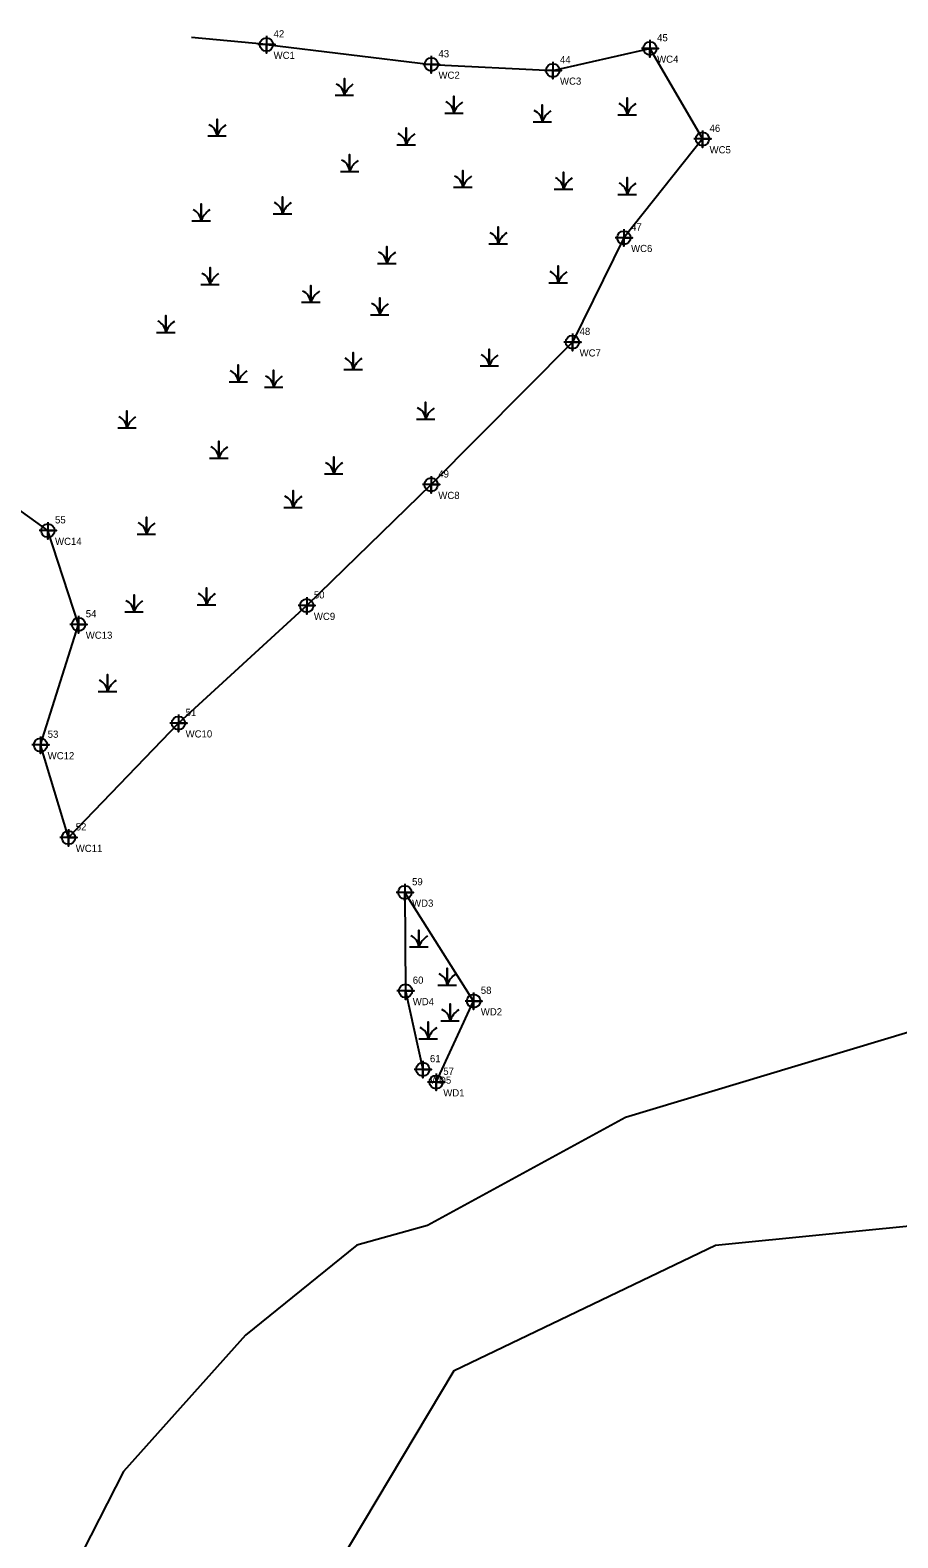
# Model space of a CAD drawing. Extents: x 2189822 to 2191198, y 387253 to 388663.
# Drawn here: x 2190593 to 2190896, y 388137 to 388663 of the extents above; entities that cross this region are included whole.
import ezdxf

# ---------------------------------------------------------------- set-up
doc = ezdxf.new("R2010")
doc.units = 0
for name, color, linetype in [('Structure020030_Alleghany', 7, 'Continuous'), ('Structure040008_Ashe', 7, 'Continuous'), ('Structure090007_Brunswick', 7, 'Continuous'), ('Structure300012_Duplin', 7, 'Continuous'), ('Structure620024_Moore', 7, 'Continuous'), ('Structure780124_Rockingham', 7, 'Continuous')]:
    doc.layers.add(name, color=color, linetype=linetype)

msp = doc.modelspace()

# ---------------------------------------------------------------- linework, layer by layer
at = {"layer": 'Structure020030_Alleghany'}
for points in [[(2190675.12, 388660.89), (2190675.12, 388654.89), (2190675.12, 388657.89), (2190678.12, 388657.89), (2190672.12, 388657.89)], [(2190808.98, 388659.55), (2190808.98, 388653.55), (2190808.98, 388656.55), (2190811.98, 388656.55), (2190805.98, 388656.55)], [(2190732.67, 388653.96), (2190732.67, 388647.96), (2190732.67, 388650.96), (2190735.67, 388650.96), (2190729.67, 388650.96)], [(2190775.08, 388651.89), (2190775.08, 388645.89), (2190775.08, 388648.89), (2190778.08, 388648.89), (2190772.08, 388648.89)], [(2190827.29, 388627.95), (2190827.29, 388621.95), (2190827.29, 388624.95), (2190830.29, 388624.95), (2190824.29, 388624.95)], [(2190799.88, 388593.51), (2190799.88, 388587.51), (2190799.88, 388590.51), (2190802.88, 388590.51), (2190796.88, 388590.51)], [(2190781.92, 388557.07), (2190781.92, 388551.07), (2190781.92, 388554.07), (2190784.92, 388554.07), (2190778.92, 388554.07)], [(2190732.61, 388507.35), (2190732.61, 388501.35), (2190732.61, 388504.35), (2190735.61, 388504.35), (2190729.61, 388504.35)], [(2190598.83, 388491.32), (2190598.83, 388485.32), (2190598.83, 388488.32), (2190601.83, 388488.32), (2190595.83, 388488.32)], [(2190689.18, 388465.15), (2190689.18, 388459.15), (2190689.18, 388462.15), (2190692.18, 388462.15), (2190686.18, 388462.15)], [(2190609.56, 388458.58), (2190609.56, 388452.58), (2190609.56, 388455.58), (2190612.56, 388455.58), (2190606.56, 388455.58)], [(2190644.41, 388424.14), (2190644.41, 388418.14), (2190644.41, 388421.14), (2190647.41, 388421.14), (2190641.41, 388421.14)], [(2190596.27, 388416.53), (2190596.27, 388410.53), (2190596.27, 388413.53), (2190599.27, 388413.53), (2190593.27, 388413.53)], [(2190606.06, 388384.2), (2190606.06, 388378.2), (2190606.06, 388381.2), (2190609.06, 388381.2), (2190603.06, 388381.2)], [(2190723.45, 388365.09), (2190723.45, 388359.09), (2190723.45, 388362.09), (2190726.45, 388362.09), (2190720.45, 388362.09)], [(2190723.69, 388330.73), (2190723.69, 388324.73), (2190723.69, 388327.73), (2190726.69, 388327.73), (2190720.69, 388327.73)], [(2190747.44, 388327.19), (2190747.44, 388321.19), (2190747.44, 388324.19), (2190750.44, 388324.19), (2190744.44, 388324.19)], [(2190729.69, 388303.35), (2190729.69, 388297.35), (2190729.69, 388300.35), (2190732.69, 388300.35), (2190726.69, 388300.35)], [(2190734.34, 388298.92), (2190734.34, 388292.92), (2190734.34, 388295.92), (2190737.34, 388295.92), (2190731.34, 388295.92)]]:
    msp.add_lwpolyline(points, dxfattribs=at)
for centre in [(2190675.12, 388657.89), (2190808.98, 388656.55), (2190732.67, 388650.96), (2190775.08, 388648.89), (2190827.29, 388624.95), (2190799.88, 388590.51), (2190781.92, 388554.07), (2190732.61, 388504.35), (2190598.83, 388488.32), (2190689.18, 388462.15), (2190609.56, 388455.58), (2190644.41, 388421.14), (2190596.27, 388413.53), (2190606.06, 388381.2), (2190723.45, 388362.09), (2190723.69, 388327.73), (2190747.44, 388324.19), (2190729.69, 388300.35), (2190734.34, 388295.92)]:
    msp.add_circle(centre, 2.34, dxfattribs=at)
at = {"layer": 'Structure300012_Duplin'}
for points in [[(2190719.63, 387525.44), (2190637.58, 387595.81), (2190615.99, 387660.63), (2190664.72, 387734.09), (2190719.01, 387832.86), (2190706.67, 387885.95), (2190672.74, 388022.38), (2190691.25, 388112.51), (2190740.6, 388195.23), (2190831.91, 388239.06), (2190949.74, 388250.79), (2191071.27, 388298.94), (2191159.49, 388358.82), (2191198.36, 388416.84)], [(2190909.02, 388316.22), (2190800.44, 388283.5), (2190731.35, 388245.85), (2190706.67, 388239.06), (2190667.81, 388207.57), (2190625.24, 388160.04), (2190596.86, 388104.48), (2190598.1, 388023), (2190601.8, 387934.1), (2190635.11, 387861.26), (2190644.98, 387808.17), (2190567.25, 387745.2), (2190533.32, 387681), (2190546.89, 387613.72), (2190580.2, 387545.81), (2190636.96, 387481.61), (2190661.02, 387459.39)]]:
    msp.add_lwpolyline(points, dxfattribs=at)
at = {"layer": 'Structure620024_Moore'}
msp.add_line((2190675.12, 388657.89), (2190648.98, 388660.35), dxfattribs=at)
for points in [[(2190675.12, 388657.89), (2190732.67, 388650.96), (2190775.08, 388648.89), (2190808.98, 388656.55), (2190827.29, 388624.95), (2190799.88, 388590.51), (2190781.92, 388554.07), (2190732.61, 388504.35), (2190689.18, 388462.15), (2190644.41, 388421.14), (2190606.06, 388381.2), (2190596.27, 388413.53), (2190609.56, 388455.58), (2190598.83, 388488.32), (2190554.41, 388520.35)], [(2190734.34, 388295.92), (2190747.44, 388324.19), (2190723.45, 388362.09), (2190723.69, 388327.73), (2190729.69, 388300.35)]]:
    msp.add_lwpolyline(points, dxfattribs=at)
at = {"layer": 'Structure780124_Rockingham'}
for p, q in [((2190702.31, 388642.87), (2190702.31, 388642.87)), ((2190740.56, 388636.7), (2190740.56, 388636.7)), ((2190771.41, 388633.61), (2190771.41, 388633.61)), ((2190801.02, 388636.08), (2190801.02, 388636.08)), ((2190657.9, 388628.67), (2190657.9, 388628.67)), ((2190723.91, 388625.58), (2190723.91, 388625.58)), ((2190704.17, 388616.32), (2190704.17, 388616.32)), ((2190743.65, 388610.77), (2190743.65, 388610.77)), ((2190778.81, 388610.15), (2190778.81, 388610.15)), ((2190801.02, 388608.3), (2190801.02, 388608.3)), ((2190680.72, 388601.51), (2190680.72, 388601.51)), ((2190652.34, 388599.04), (2190652.34, 388599.04)), ((2190755.99, 388591.01), (2190755.99, 388591.01)), ((2190717.12, 388584.22), (2190717.12, 388584.22)), ((2190655.43, 388576.82), (2190655.43, 388576.82)), ((2190776.96, 388577.43), (2190776.96, 388577.43)), ((2190690.59, 388570.64), (2190690.59, 388570.64)), ((2190714.65, 388566.32), (2190714.65, 388566.32)), ((2190640.01, 388560.15), (2190640.01, 388560.15)), ((2190705.4, 388547.18), (2190705.4, 388547.18)), ((2190752.9, 388548.42), (2190752.9, 388548.42)), ((2190665.3, 388542.86), (2190665.3, 388542.86)), ((2190677.64, 388541.01), (2190677.64, 388541.01)), ((2190730.69, 388529.9), (2190730.69, 388529.9)), ((2190626.43, 388526.81), (2190626.43, 388526.81)), ((2190658.51, 388516.32), (2190658.51, 388516.32)), ((2190698.61, 388510.76), (2190698.61, 388510.76)), ((2190684.42, 388499.03), (2190684.42, 388499.03)), ((2190633.22, 388489.77), (2190633.22, 388489.77)), ((2190654.19, 388465.08), (2190654.19, 388465.08)), ((2190628.9, 388462.61), (2190628.9, 388462.61)), ((2190619.65, 388434.83), (2190619.65, 388434.83)), ((2190728.34, 388345.73), (2190728.34, 388345.73)), ((2190738.21, 388332.42), (2190738.21, 388332.42)), ((2190739.22, 388319.92), (2190739.22, 388319.92)), ((2190731.56, 388313.68), (2190731.56, 388313.68))]:
    msp.add_line(p, q, dxfattribs=at)
for points in [[(2190699.09, 388640.19), (2190702.32, 388640.19), (2190702.32, 388646.11), (2190702.32, 388640.19), (2190705.54, 388640.19)], [(2190737.34, 388634.02), (2190740.56, 388634.02), (2190740.56, 388639.94), (2190740.56, 388634.02), (2190743.79, 388634.02)], [(2190797.8, 388633.4), (2190801.02, 388633.4), (2190801.02, 388639.32), (2190801.02, 388633.4), (2190804.25, 388633.4)], [(2190768.18, 388630.93), (2190771.41, 388630.93), (2190771.41, 388636.85), (2190771.41, 388630.93), (2190774.64, 388630.93)], [(2190654.67, 388626), (2190657.9, 388626), (2190657.9, 388631.91), (2190657.9, 388626), (2190661.12, 388626)], [(2190720.68, 388622.91), (2190723.91, 388622.91), (2190723.91, 388628.83), (2190723.91, 388622.91), (2190727.13, 388622.91)], [(2190700.94, 388613.65), (2190704.17, 388613.65), (2190704.17, 388619.57), (2190704.17, 388613.65), (2190707.39, 388613.65)], [(2190740.42, 388608.09), (2190743.65, 388608.09), (2190743.65, 388614.01), (2190743.65, 388608.09), (2190746.87, 388608.09)], [(2190775.59, 388607.48), (2190778.81, 388607.48), (2190778.81, 388613.39), (2190778.81, 388607.48), (2190782.04, 388607.48)], [(2190797.8, 388605.62), (2190801.02, 388605.62), (2190801.02, 388611.54), (2190801.02, 388605.62), (2190804.25, 388605.62)], [(2190649.12, 388596.36), (2190652.34, 388596.36), (2190652.34, 388602.28), (2190652.34, 388596.36), (2190655.57, 388596.36)], [(2190677.5, 388598.83), (2190680.72, 388598.83), (2190680.72, 388604.75), (2190680.72, 388598.83), (2190683.95, 388598.83)], [(2190752.76, 388588.34), (2190755.99, 388588.34), (2190755.99, 388594.26), (2190755.99, 388588.34), (2190759.21, 388588.34)], [(2190713.9, 388581.55), (2190717.12, 388581.55), (2190717.12, 388587.47), (2190717.12, 388581.55), (2190720.35, 388581.55)], [(2190773.74, 388574.76), (2190776.96, 388574.76), (2190776.96, 388580.68), (2190776.96, 388574.76), (2190780.19, 388574.76)], [(2190652.2, 388574.14), (2190655.43, 388574.14), (2190655.43, 388580.06), (2190655.43, 388574.14), (2190658.65, 388574.14)], [(2190687.37, 388567.97), (2190690.59, 388567.97), (2190690.59, 388573.89), (2190690.59, 388567.97), (2190693.82, 388567.97)], [(2190711.43, 388563.65), (2190714.65, 388563.65), (2190714.65, 388569.56), (2190714.65, 388563.65), (2190717.88, 388563.65)], [(2190636.78, 388557.47), (2190640.01, 388557.47), (2190640.01, 388563.39), (2190640.01, 388557.47), (2190643.23, 388557.47)], [(2190702.17, 388544.51), (2190705.4, 388544.51), (2190705.4, 388550.43), (2190705.4, 388544.51), (2190708.63, 388544.51)], [(2190749.68, 388545.75), (2190752.9, 388545.75), (2190752.9, 388551.66), (2190752.9, 388545.75), (2190756.13, 388545.75)], [(2190662.07, 388540.19), (2190665.3, 388540.19), (2190665.3, 388546.11), (2190665.3, 388540.19), (2190668.53, 388540.19)], [(2190674.41, 388538.34), (2190677.64, 388538.34), (2190677.64, 388544.25), (2190677.64, 388538.34), (2190680.86, 388538.34)], [(2190727.47, 388527.23), (2190730.69, 388527.23), (2190730.69, 388533.14), (2190730.69, 388527.23), (2190733.92, 388527.23)], [(2190623.21, 388524.14), (2190626.43, 388524.14), (2190626.43, 388530.06), (2190626.43, 388524.14), (2190629.66, 388524.14)], [(2190655.29, 388513.64), (2190658.51, 388513.64), (2190658.51, 388519.56), (2190658.51, 388513.64), (2190661.74, 388513.64)], [(2190695.39, 388508.09), (2190698.61, 388508.09), (2190698.61, 388514.01), (2190698.61, 388508.09), (2190701.84, 388508.09)], [(2190681.2, 388496.36), (2190684.42, 388496.36), (2190684.42, 388502.28), (2190684.42, 388496.36), (2190687.65, 388496.36)], [(2190629.99, 388487.1), (2190633.22, 388487.1), (2190633.22, 388493.02), (2190633.22, 388487.1), (2190636.45, 388487.1)], [(2190625.68, 388459.94), (2190628.9, 388459.94), (2190628.9, 388465.86), (2190628.9, 388459.94), (2190632.13, 388459.94)], [(2190650.97, 388462.41), (2190654.2, 388462.41), (2190654.2, 388468.33), (2190654.2, 388462.41), (2190657.42, 388462.41)], [(2190616.42, 388432.16), (2190619.65, 388432.16), (2190619.65, 388438.08), (2190619.65, 388432.16), (2190622.87, 388432.16)], [(2190725.11, 388343.05), (2190728.34, 388343.05), (2190728.34, 388348.97), (2190728.34, 388343.05), (2190731.56, 388343.05)], [(2190734.98, 388329.75), (2190738.21, 388329.75), (2190738.21, 388335.67), (2190738.21, 388329.75), (2190741.44, 388329.75)], [(2190735.99, 388317.25), (2190739.22, 388317.25), (2190739.22, 388323.17), (2190739.22, 388317.25), (2190742.44, 388317.25)], [(2190728.34, 388311), (2190731.56, 388311), (2190731.56, 388316.92), (2190731.56, 388311), (2190734.79, 388311)]]:
    msp.add_lwpolyline(points, dxfattribs=at)
for centre, radius, start, end in [((2190697.72, 388639.86), 4.61, 4.1403, 67.535), ((2190709.16, 388637.92), 7.21, 122.1274, 161.6222), ((2190735.96, 388633.69), 4.61, 4.1403, 67.535), ((2190747.4, 388631.75), 7.21, 122.1274, 161.6222), ((2190766.81, 388630.6), 4.61, 4.1403, 67.535), ((2190778.25, 388628.66), 7.21, 122.1274, 161.6222), ((2190796.42, 388633.07), 4.61, 4.1403, 67.535), ((2190807.86, 388631.13), 7.21, 122.1274, 161.6222), ((2190653.3, 388625.66), 4.61, 4.1403, 67.535), ((2190664.74, 388623.72), 7.21, 122.1274, 161.6222), ((2190719.31, 388622.58), 4.61, 4.1403, 67.535), ((2190730.75, 388620.64), 7.21, 122.1274, 161.6222), ((2190699.57, 388613.32), 4.61, 4.1403, 67.535), ((2190711.01, 388611.38), 7.21, 122.1274, 161.6222), ((2190739.05, 388607.76), 4.61, 4.1403, 67.535), ((2190750.49, 388605.82), 7.21, 122.1274, 161.6222), ((2190774.21, 388607.14), 4.61, 4.1403, 67.535), ((2190785.65, 388605.2), 7.21, 122.1274, 161.6222), ((2190796.42, 388605.29), 4.61, 4.1403, 67.535), ((2190807.86, 388603.35), 7.21, 122.1274, 161.6222), ((2190676.12, 388598.5), 4.61, 4.1403, 67.535), ((2190687.56, 388596.56), 7.21, 122.1274, 161.6222), ((2190647.74, 388596.03), 4.61, 4.1403, 67.535), ((2190659.19, 388594.09), 7.21, 122.1274, 161.6222), ((2190751.39, 388588.01), 4.61, 4.1403, 67.535), ((2190762.83, 388586.07), 7.21, 122.1274, 161.6222), ((2190712.52, 388581.22), 4.61, 4.1403, 67.535), ((2190723.96, 388579.28), 7.21, 122.1274, 161.6222), ((2190650.83, 388573.81), 4.61, 4.1403, 67.535), ((2190662.27, 388571.87), 7.21, 122.1274, 161.6222), ((2190772.36, 388574.43), 4.61, 4.1403, 67.535), ((2190783.8, 388572.49), 7.21, 122.1274, 161.6222), ((2190685.99, 388567.64), 4.61, 4.1403, 67.535), ((2190697.43, 388565.7), 7.21, 122.1274, 161.6222), ((2190710.05, 388563.31), 4.61, 4.1403, 67.535), ((2190721.49, 388561.37), 7.21, 122.1274, 161.6222), ((2190635.41, 388557.14), 4.61, 4.1403, 67.535), ((2190646.85, 388555.2), 7.21, 122.1274, 161.6222), ((2190748.3, 388545.41), 4.61, 4.1403, 67.535), ((2190759.74, 388543.47), 7.21, 122.1274, 161.6222), ((2190660.7, 388539.86), 4.61, 4.1403, 67.535), ((2190672.14, 388537.92), 7.21, 122.1274, 161.6222), ((2190700.8, 388544.18), 4.61, 4.1403, 67.535), ((2190712.24, 388542.24), 7.21, 122.1274, 161.6222), ((2190673.04, 388538), 4.61, 4.1403, 67.535), ((2190684.48, 388536.06), 7.21, 122.1274, 161.6222), ((2190621.83, 388523.81), 4.61, 4.1403, 67.535), ((2190633.27, 388521.87), 7.21, 122.1274, 161.6222), ((2190726.09, 388526.89), 4.61, 4.1403, 67.535), ((2190737.53, 388524.95), 7.21, 122.1274, 161.6222), ((2190653.91, 388513.31), 4.61, 4.1403, 67.535), ((2190665.35, 388511.37), 7.21, 122.1274, 161.6222), ((2190694.01, 388507.76), 4.61, 4.1403, 67.535), ((2190705.45, 388505.82), 7.21, 122.1274, 161.6222), ((2190679.82, 388496.03), 4.61, 4.1403, 67.535), ((2190691.27, 388494.09), 7.21, 122.1274, 161.6222), ((2190628.62, 388486.77), 4.61, 4.1403, 67.535), ((2190640.06, 388484.83), 7.21, 122.1274, 161.6222), ((2190649.6, 388462.07), 4.61, 4.1403, 67.535), ((2190661.04, 388460.13), 7.21, 122.1274, 161.6222), ((2190624.3, 388459.61), 4.61, 4.1403, 67.535), ((2190635.74, 388457.67), 7.21, 122.1274, 161.6222), ((2190615.05, 388431.83), 4.61, 4.1403, 67.535), ((2190626.49, 388429.89), 7.21, 122.1274, 161.6222), ((2190723.74, 388342.72), 4.61, 4.1403, 67.535), ((2190735.18, 388340.78), 7.21, 122.1274, 161.6222), ((2190733.61, 388329.41), 4.61, 4.1403, 67.535), ((2190745.05, 388327.48), 7.21, 122.1274, 161.6222), ((2190734.62, 388316.92), 4.61, 4.1403, 67.535), ((2190746.06, 388314.98), 7.21, 122.1274, 161.6222), ((2190726.96, 388310.67), 4.61, 4.1403, 67.535), ((2190738.4, 388308.73), 7.21, 122.1274, 161.6222)]:
    msp.add_arc(centre, radius, start, end, dxfattribs=at)

# ---------------------------------------------------------------- texts
at = {"layer": 'Structure040008_Ashe'}
for s, p in [('42', (2190677.62, 388660.39)), ('45', (2190811.48, 388659.05)), ('43', (2190735.17, 388653.46)), ('44', (2190777.58, 388651.39)), ('46', (2190829.79, 388627.45)), ('47', (2190802.38, 388593.01)), ('48', (2190784.42, 388556.57)), ('49', (2190735.11, 388506.85)), ('55', (2190601.33, 388490.82)), ('50', (2190691.68, 388464.65)), ('54', (2190612.06, 388458.08)), ('51', (2190646.91, 388423.64)), ('53', (2190598.77, 388416.03)), ('52', (2190608.56, 388383.7)), ('59', (2190725.95, 388364.59)), ('60', (2190726.19, 388330.23)), ('58', (2190749.94, 388326.69)), ('61', (2190732.19, 388302.85)), ('57', (2190736.84, 388298.42))]:
    msp.add_text(s, height=2.5, dxfattribs=at).set_placement(p)
at = {"layer": 'Structure090007_Brunswick'}
for s, p in [('WC1', (2190677.62, 388652.89)), ('WC4', (2190811.48, 388651.55)), ('WC2', (2190735.17, 388645.96)), ('WC3', (2190777.58, 388643.89)), ('WC5', (2190829.79, 388619.95)), ('WC6', (2190802.38, 388585.51)), ('WC7', (2190784.42, 388549.07)), ('WC8', (2190735.11, 388499.35)), ('WC14', (2190601.33, 388483.32)), ('WC9', (2190691.68, 388457.15)), ('WC13', (2190612.06, 388450.58)), ('WC10', (2190646.91, 388416.14)), ('WC12', (2190598.77, 388408.53)), ('WC11', (2190608.56, 388376.2)), ('WD3', (2190725.95, 388357.09)), ('WD4', (2190726.19, 388322.73)), ('WD2', (2190749.94, 388319.19)), ('WD5', (2190732.19, 388295.35)), ('WD1', (2190736.84, 388290.92))]:
    msp.add_text(s, height=2.5, dxfattribs=at).set_placement(p)

doc.saveas('drawing.dxf')
